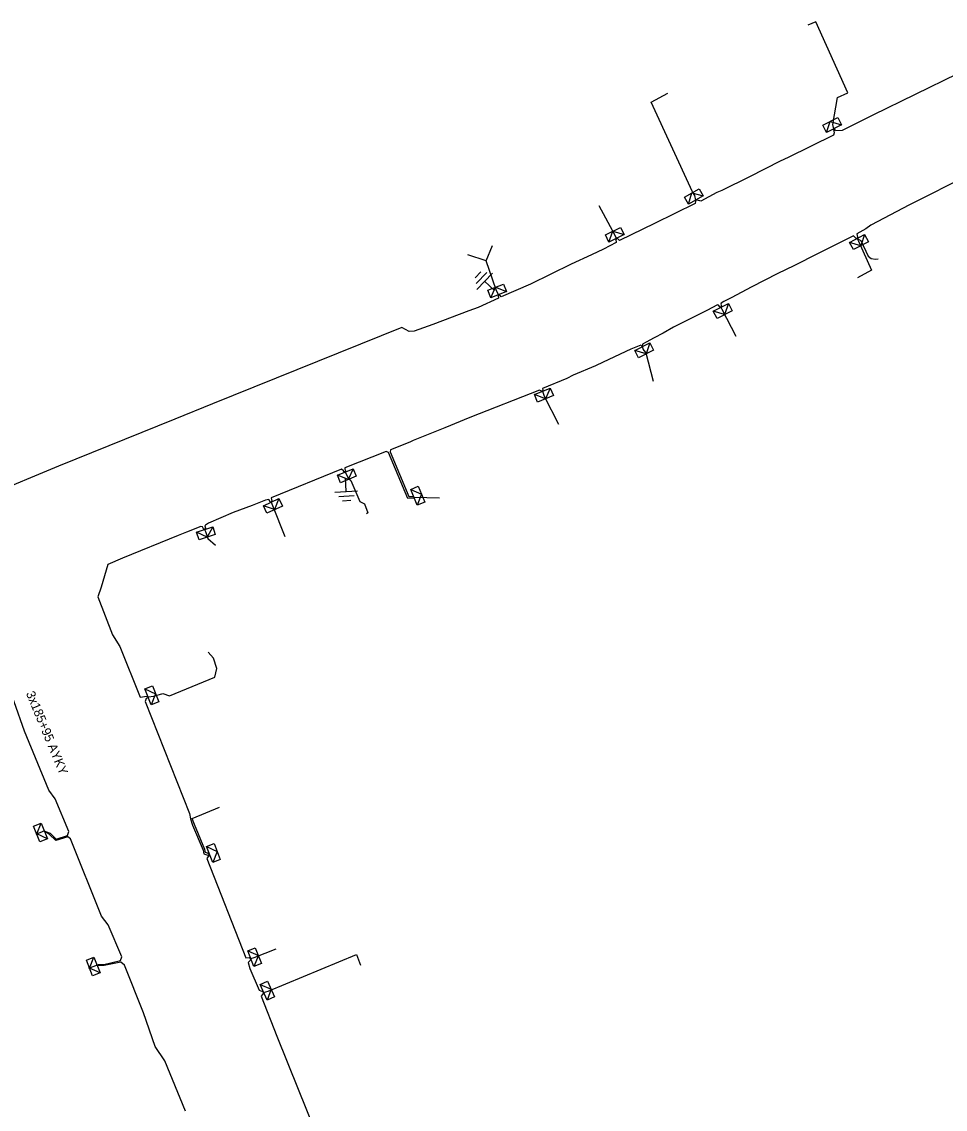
# Model space of a CAD drawing. Extents: x -540028 to -538776, y -1157064 to -1155670.
# Drawn here: x -539834.1 to -539732.2, y -1156040.4 to -1155920.3 of the extents above; entities that cross this region are included whole.
import ezdxf

# ---------------------------------------------------------------- set-up
doc = ezdxf.new("R2010")
doc.units = 0
for name, color, linetype in [('Vrstva 15', 7, 'Continuous'), ('Vrstva 2', 7, 'Continuous'), ('Vrstva 31', 7, 'Continuous'), ('Vrstva 5', 7, 'Continuous'), ('Vrstva 52', 7, 'Continuous'), ('Vrstva 59', 7, 'Continuous'), ('Vrstva 6', 7, 'Continuous')]:
    doc.layers.add(name, color=color, linetype=linetype)

# ---------------------------------------------------------------- blocks, each defined once
blk = doc.blocks.new('23')
at = {"layer": 'Vrstva 2'}
blk.add_lwpolyline([(1.875, -1.8), (-1.875, -1.8), (-1.875, 0), (1.875, 0)], close=True, dxfattribs=at)
blk.add_lwpolyline([(1.875, 0), (0, -1.8), (-1.875, 0)], dxfattribs=at)
blk = doc.blocks.new('11')
at = {"layer": 'Vrstva 2'}
for p, q in [((0, -4.3), (0, -1.3)), ((-2.5, -4.3), (2.5, -4.3)), ((-1.7, -5.3), (1.7, -5.3)), ((-0.9, -6.3), (0.9, -6.3))]:
    blk.add_line(p, q, dxfattribs=at)

msp = doc.modelspace()

# ---------------------------------------------------------------- linework, layer by layer
at = {"layer": 'Vrstva 5'}
for points in [[(-539730.86, -1155926.09), (-539740.2, -1155930.66), (-539743.57, -1155932.36), (-539744.32, -1155932.4), (-539744.4, -1155932.2), (-539744.48, -1155932.16), (-539744.53, -1155932.24), (-539744.47, -1155932.61), (-539744.52, -1155932.86), (-539749.52, -1155935.32), (-539750.42, -1155935.76), (-539753.8, -1155937.46), (-539756.84, -1155938.97), (-539757.41, -1155939.19), (-539759.19, -1155940.16), (-539759.55, -1155940.06), (-539759.72, -1155940.03), (-539759.77, -1155940.18), (-539759.78, -1155940.42), (-539764.29, -1155942.64), (-539768.14, -1155944.51), (-539768.32, -1155944.3), (-539768.47, -1155944.27), (-539768.55, -1155944.4), (-539768.51, -1155944.72), (-539769.92, -1155945.45), (-539771.24, -1155946.07), (-539773.47, -1155947.13), (-539777.98, -1155949.31), (-539781.2, -1155950.72), (-539781.36, -1155950.53), (-539781.49, -1155950.49), (-539781.55, -1155950.6), (-539781.51, -1155950.86), (-539783.74, -1155951.89), (-539784.77, -1155952.27), (-539788.76, -1155953.79), (-539790.81, -1155954.51), (-539791.36, -1155954.55), (-539792.18, -1155954.09), (-539813.06, -1155962.54), (-539817.21, -1155964.23), (-539830.05, -1155969.43), (-539837.85, -1155972.64)], [(-539729.55, -1155937.24), (-539736.14, -1155940.56), (-539740.42, -1155942.79), (-539740.95, -1155943.23), (-539741.96, -1155943.78), (-539741.87, -1155944.15), (-539741.92, -1155944.28), (-539742.06, -1155944.25), (-539742.32, -1155943.97), (-539747.09, -1155946.36), (-539748.02, -1155946.84), (-539748.92, -1155947.28), (-539750.67, -1155948.16), (-539753.63, -1155949.67), (-539755.75, -1155950.79), (-539756.63, -1155951.25), (-539756.93, -1155951.41), (-539756.98, -1155951.53), (-539756.89, -1155951.76), (-539756.96, -1155951.88), (-539757.09, -1155951.83), (-539757.21, -1155951.64), (-539757.32, -1155951.61), (-539758.52, -1155952.24), (-539762.18, -1155954.07), (-539763.32, -1155954.73), (-539764.33, -1155955.25), (-539765.21, -1155955.71), (-539765.6, -1155955.95), (-539765.63, -1155956.22), (-539765.81, -1155956.05), (-539766.9, -1155956.51), (-539769.97, -1155957.93), (-539770.78, -1155958.33), (-539773.26, -1155959.36), (-539773.98, -1155959.74), (-539776.65, -1155960.86), (-539776.6, -1155961.04), (-539776.66, -1155961.15), (-539776.77, -1155961.12), (-539776.98, -1155961.01), (-539784.65, -1155964.04), (-539787.43, -1155965.18), (-539790.92, -1155966.59), (-539791.29, -1155966.75), (-539793.42, -1155967.6), (-539793.46, -1155967.84), (-539791.39, -1155972.78), (-539790.94, -1155972.76), (-539790.83, -1155972.85), (-539790.9, -1155972.96), (-539791.52, -1155972.99), (-539793.65, -1155967.9), (-539793.89, -1155967.8), (-539798.47, -1155969.61), (-539798.45, -1155969.76), (-539798.35, -1155969.97), (-539798.42, -1155970.06), (-539798.54, -1155970.04), (-539798.61, -1155969.92), (-539798.84, -1155969.76), (-539806.59, -1155972.93), (-539806.52, -1155973.28), (-539806.59, -1155973.4), (-539806.71, -1155973.35), (-539806.84, -1155973.11), (-539807.22, -1155973.19), (-539808.7, -1155973.76), (-539810.78, -1155974.55), (-539813.5, -1155975.73), (-539813.86, -1155975.92), (-539813.9, -1155976), (-539813.86, -1155976.28), (-539813.94, -1155976.4), (-539814.06, -1155976.34), (-539814.18, -1155976.11), (-539814.34, -1155976.08), (-539815.95, -1155976.7)], [(-539815.95, -1155976.7), (-539816.87, -1155977.08), (-539823, -1155979.59), (-539824.62, -1155980.26), (-539825.34, -1155982.77), (-539825.73, -1155983.85), (-539824.12, -1155988.03), (-539823.28, -1155989.34), (-539821.07, -1155994.92), (-539820.32, -1155994.8), (-539820.18, -1155994.89), (-539820.26, -1155995), (-539820.39, -1155995.08), (-539820.52, -1155995.41), (-539815.6, -1156007.77), (-539815.49, -1156008.37), (-539815.26, -1156009.04), (-539814.11, -1156011.8), (-539814.01, -1156012.21), (-539813.6, -1156012.38), (-539813.39, -1156012.29), (-539813.62, -1156012.61), (-539813.69, -1156012.73), (-539809.39, -1156023.7), (-539809.04, -1156023.65), (-539808.84, -1156023.79), (-539808.9, -1156024.01), (-539809.15, -1156024.23), (-539808.94, -1156024.87), (-539807.93, -1156027.27), (-539807.54, -1156027.43), (-539807.43, -1156027.52), (-539807.47, -1156027.63), (-539807.7, -1156027.93), (-539805.98, -1156032.34), (-539803.6, -1156038.19), (-539801.16, -1156044.31)], [(-539816.06, -1156040.62), (-539818.34, -1156035.09), (-539819.39, -1156033.5), (-539820.7, -1156029.78), (-539822.79, -1156024.51), (-539823.19, -1156024.18), (-539825.03, -1156024.54), (-539825.64, -1156024.57), (-539825.81, -1156024.5), (-539825.64, -1156024.44), (-539825.05, -1156024.44), (-539823.23, -1156024.01), (-539823.09, -1156023.6), (-539824.59, -1156020.07), (-539825.33, -1156019.11), (-539828.75, -1156010.56), (-539829.03, -1156010.34), (-539830.37, -1156010.75), (-539831.11, -1156010.06), (-539831.51, -1156009.79), (-539831.63, -1156009.7), (-539831.49, -1156009.74), (-539831, -1156009.95), (-539830.33, -1156010.59), (-539829.08, -1156010.2), (-539828.91, -1156009.76), (-539830.43, -1156006.16), (-539831.12, -1156005.18), (-539833.81, -1155998.68), (-539836.11, -1155992.19)]]:
    msp.add_lwpolyline(points, dxfattribs=at)
at = {"layer": 'Vrstva 52'}
for points in [[(-539744.48, -1155932.16), (-539744.61, -1155931.69), (-539744.07, -1155928.73), (-539742.96, -1155928.19), (-539746.48, -1155920.35), (-539747.35, -1155920.74)], [(-539759.72, -1155940.03), (-539759.85, -1155939.55), (-539760.08, -1155939.12), (-539764.64, -1155929.22), (-539762.81, -1155928.25)], [(-539768.47, -1155944.27), (-539768.68, -1155943.87), (-539770.38, -1155940.68)], [(-539741.92, -1155944.28), (-539741.77, -1155944.57), (-539740.33, -1155947.78), (-539741.88, -1155948.61)], [(-539741.92, -1155944.28), (-539741.51, -1155944.51), (-539740.72, -1155946.22), (-539740.39, -1155946.49), (-539739.9, -1155946.57), (-539739.6, -1155946.54)], [(-539781.49, -1155950.49), (-539781.76, -1155949.96), (-539782.88, -1155946.76)], [(-539756.96, -1155951.88), (-539756.87, -1155952.08), (-539755.32, -1155955.08)], [(-539765.63, -1155956.22), (-539765.52, -1155956.52), (-539765.48, -1155956.64), (-539765.24, -1155956.89), (-539764.43, -1155960.05)], [(-539776.66, -1155961.15), (-539776.48, -1155961.68), (-539774.87, -1155964.79)], [(-539798.42, -1155970.06), (-539798.09, -1155970.75), (-539797.81, -1155971), (-539796.81, -1155973.31), (-539796.3, -1155973.57), (-539795.93, -1155974.57), (-539796.09, -1155974.69)], [(-539806.59, -1155973.4), (-539806.45, -1155973.76), (-539805.07, -1155977.17)], [(-539813.94, -1155976.4), (-539813.86, -1155976.64), (-539813.57, -1155977.4), (-539812.73, -1155978.15)], [(-539820.18, -1155994.89), (-539819.54, -1155994.83), (-539818.57, -1155994.52), (-539817.81, -1155994.79), (-539812.8, -1155992.7), (-539812.59, -1155991.75), (-539812.96, -1155990.6), (-539813.56, -1155989.94)], [(-539813.39, -1156012.29), (-539813.61, -1156012.16), (-539813.84, -1156012.07), (-539813.92, -1156011.74), (-539815.07, -1156008.97), (-539815.3, -1156008.31), (-539812.31, -1156007.07)], [(-539808.84, -1156023.79), (-539808.48, -1156023.68), (-539806.04, -1156022.72)], [(-539807.43, -1156027.52), (-539806.92, -1156027.4), (-539797.19, -1156023.32), (-539796.73, -1156024.51)]]:
    msp.add_lwpolyline(points, dxfattribs=at)
at = {"layer": 'Vrstva 59'}
for points in [[(-539782.88, -1155946.76), (-539782.15, -1155945.07)], [(-539782.88, -1155946.76), (-539784.89, -1155946.1)], [(-539790.83, -1155972.85), (-539788.01, -1155972.93)], [(-539831.63, -1156009.7), (-539832.57, -1156010.07)], [(-539825.81, -1156024.5), (-539826.74, -1156024.87)]]:
    msp.add_lwpolyline(points, dxfattribs=at)

# ---------------------------------------------------------------- block references
at = {"layer": 'Vrstva 15', "xscale": 0.5}
for p, yscale, rotation in [((-539781.49, -1155950.49), 0.49999999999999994, -134.0596777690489), ((-539798.42, -1155970.06), 0.5000000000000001, 3.0066722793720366)]:
    msp.add_blockref('11', p, dxfattribs=dict(at, yscale=yscale, rotation=rotation))
at = {"layer": 'Vrstva 31'}
for p, xscale, yscale, rotation in [((-539744.48, -1155932.16), 0.5, 0.5, -153.01482507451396), ((-539759.72, -1155940.03), 0.5, 0.5, -149.89860549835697), ((-539768.47, -1155944.27), 0.5, 0.5, -153.82154450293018), ((-539741.92, -1155944.28), 0.5000000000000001, 0.5, 27.76608322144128), ((-539781.49, -1155950.49), 0.5, 0.5, -158.3127416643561), ((-539756.96, -1155951.88), 0.5, 0.5, 27.19232493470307), ((-539765.63, -1155956.22), 0.5, 0.5, 27.02622206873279), ((-539776.66, -1155961.15), 0.5, 0.5, 22.44668883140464), ((-539798.42, -1155970.06), 0.5, 0.5, 22.172797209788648), ((-539790.83, -1155972.85), 0.49999999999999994, 0.5000000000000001, 112.28660275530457), ((-539806.59, -1155973.4), 0.5, 0.5, 24.880388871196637), ((-539813.94, -1155976.4), 0.5, 0.5, 18.25751666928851), ((-539820.18, -1155994.89), 0.5, 0.49999999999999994, 111.75538330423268), ((-539831.63, -1156009.7), 0.5, 0.5, -68.62571946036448), ((-539813.39, -1156012.29), 0.5, 0.5, 111.22713057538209), ((-539808.84, -1156023.79), 0.5, 0.5, 111.71802496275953), ((-539825.81, -1156024.5), 0.5000000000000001, 0.5, -68.62746386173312), ((-539807.43, -1156027.52), 0.5, 0.5, 114.27578605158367)]:
    msp.add_blockref('23', p, dxfattribs=dict(at, xscale=xscale, yscale=yscale, rotation=rotation))

# ---------------------------------------------------------------- texts
at = {"layer": 'Vrstva 6'}
msp.add_text('3x185+95 AYKY', height=1, rotation=292.506, dxfattribs=at).set_placement((-539833.68, -1155994.5))

doc.saveas('drawing.dxf')
